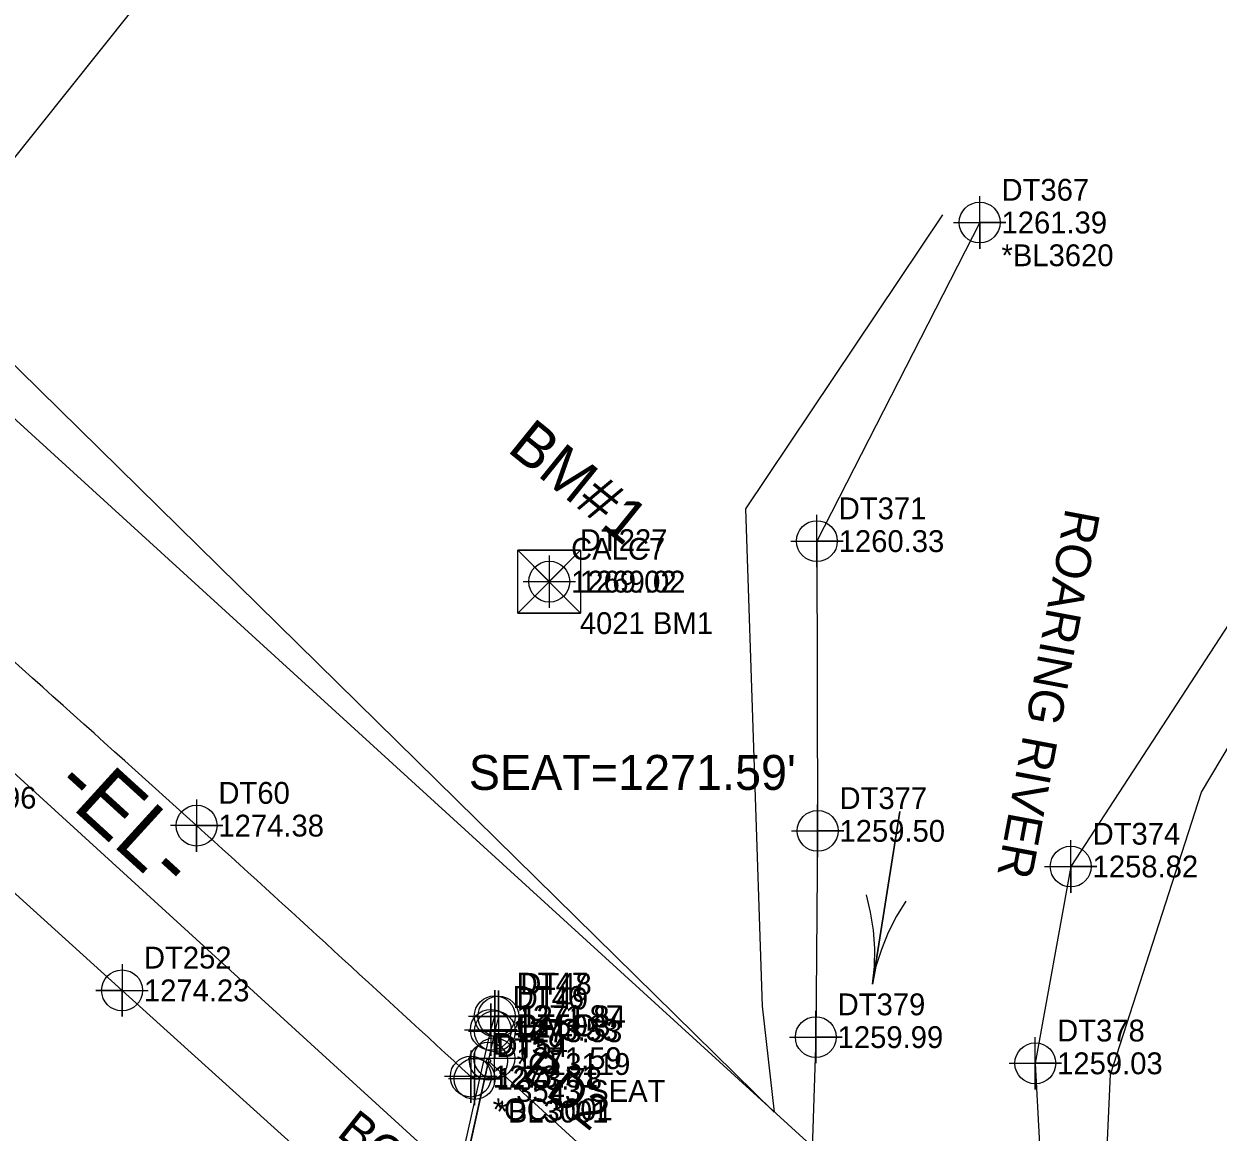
# Model space of a CAD drawing. Extents: x 1390773 to 1392296, y 959928 to 960736.
# Drawn here: x 1391507.3 to 1391644.1, y 960403.3 to 960530.2 of the extents above; entities that cross this region are included whole.
import ezdxf

# ---------------------------------------------------------------- set-up
doc = ezdxf.new("R2010")
doc.units = 0
for name, color, linetype in [('Cogo Default Point CELL', 7, 'Continuous'), ('COGO Default Point Elevation', 7, 'Continuous'), ('COGO Default Point Number', 7, 'Continuous'), ('CTL Bench Mark CELL', 7, 'Continuous'), ('CTL Bench Mark Cogo Comment', 7, 'Continuous'), ('CTL Bench Mark Cogo Elevation', 7, 'Continuous'), ('CTL Bench Mark Cogo Number', 7, 'Continuous'), ('CTL Bench Mark Text', 7, 'Continuous'), ('Default', 7, 'Continuous'), ('Exist Horizontal Alignment', 7, 'Continuous'), ('Exist Horizontal Alignment Direction Label', 7, 'Continuous'), ('Exist Hydro Jurisdictional Stream or Body of Water', 7, 'Continuous'), ('Exist Hydro River Flow Arrow CELL', 7, 'Continuous'), ('Exist Hydro Stream or Body of Water Cogo Comment', 7, 'Continuous'), ('Exist Hydro Stream or Body of Water Cogo Elevation', 7, 'Continuous'), ('Exist Hydro Stream or Body of Water Cogo Number', 7, 'Continuous'), ('Exist Hydro Stream or Body of Water Cogo Point CELL', 7, 'Continuous'), ('Exist Hydro Stream or Body of Water Text', 7, 'Continuous'), ('Exist Other Culture Located Object CELL', 7, 'Continuous'), ('Exist Other Culture Located Object Text', 7, 'Continuous'), ('Exist Right of Way Line', 7, 'Continuous'), ('Exist Roads EOP', 7, 'Continuous'), ('Exist Roads EOP Cogo Comment', 7, 'Continuous'), ('Exist Roads EOP Cogo Elevation', 7, 'Continuous'), ('Exist Roads EOP Cogo Number', 7, 'Continuous'), ('Exist Roads EOP Cogo Point CELL', 7, 'Continuous'), ('Exist Roads EOT', 7, 'Continuous'), ('Exist Roads EOT Cogo Elevation', 7, 'Continuous'), ('Exist Roads EOT Cogo Number', 7, 'Continuous'), ('Exist Roads EOT Cogo Point CELL', 7, 'Continuous'), ('Exist Structure Major Bridge Seat Top Elevation', 7, 'Continuous'), ('Exist Structure Major Bridge WW', 7, 'Continuous'), ('Exist Structure Major Bridge WW Cogo Comment', 7, 'Continuous'), ('Exist Structure Major Bridge WW Cogo Elevation', 7, 'Continuous'), ('Exist Structure Major Bridge WW Cogo Number', 7, 'Continuous'), ('Exist Structure Major Bridge WW Cogo Point CELL', 7, 'Continuous'), ('Exist Structure Major Deck Tunnel Box Culvert', 7, 'Continuous'), ('Exist Utilities Sanitary Sewer Manhole Cogo Comment', 7, 'Continuous'), ('Exist Utilities Sanitary Sewer Manhole Cogo Elevation', 7, 'Continuous'), ('Exist Utilities Sanitary Sewer Manhole Cogo Number', 7, 'Continuous'), ('Exist Vegetation Woods Line', 7, 'Continuous')]:
    doc.layers.add(name, color=color, linetype=linetype)

msp = doc.modelspace()

# ---------------------------------------------------------------- linework, layer by layer
at = {"layer": 'Cogo Default Point CELL'}
for points in [[(1391567.49, 960469.31), (1391567.49, 960466.31)], [(1391564.49, 960466.31), (1391567.49, 960466.31)], [(1391567.49, 960466.31), (1391570.49, 960466.31)], [(1391567.49, 960466.31), (1391567.49, 960463.31)], [(1391561.2, 960414.76), (1391561.2, 960411.76)], [(1391558.2, 960411.76), (1391561.2, 960411.76)], [(1391561.2, 960411.76), (1391564.2, 960411.76)], [(1391561.2, 960411.76), (1391561.2, 960408.76)]]:
    msp.add_lwpolyline(points, dxfattribs=at)
for centre in [(1391567.49, 960466.31), (1391561.2, 960411.76)]:
    msp.add_circle(centre, 2.34, dxfattribs=at)
at = {"layer": 'CTL Bench Mark CELL'}
msp.add_line((1391567.49, 960466.31), (1391567.49, 960466.31), dxfattribs=at)
msp.add_lwpolyline([(1391563.89, 960469.9), (1391571.08, 960469.9), (1391571.08, 960462.71), (1391563.89, 960462.71)], close=True, dxfattribs=at)
for points in [[(1391571.08, 960469.9), (1391563.89, 960462.71), (1391567.49, 960466.3), (1391571.08, 960462.71), (1391563.89, 960469.9)], [(1391567.49, 960466.3), (1391571.08, 960469.9), (1391563.89, 960469.9), (1391567.49, 960466.3)], [(1391567.49, 960466.3), (1391563.89, 960462.71), (1391571.08, 960462.71), (1391567.49, 960466.3)]]:
    msp.add_lwpolyline(points, dxfattribs=at)
at = {"layer": 'Default'}
msp.add_lwpolyline([(1391484.04, 960487.03), (1391533.92, 960549.51), (1391454.08, 960613.24)], dxfattribs=at)
at = {"layer": 'Exist Horizontal Alignment'}
msp.add_line((1391337.61, 960598.13), (1391677.68, 960288.07), dxfattribs=at)
at = {"layer": 'Exist Hydro Jurisdictional Stream or Body of Water'}
for points in [[(1391616.77, 960507.42), (1391598.13, 960470.95), (1391598.22, 960437.78), (1391598.01, 960414.17), (1391597.19, 960388.55), (1391595.21, 960379.53)], [(1391649.06, 960494.04), (1391648.63, 960466.55), (1391627.2, 960433.7), (1391623.14, 960411.17), (1391625.85, 960360.36), (1391624.5, 960352.95)]]:
    msp.add_lwpolyline(points, dxfattribs=at)
at = {"layer": 'Exist Hydro River Flow Arrow CELL'}
msp.add_line((1391606.06, 960430.1), (1391606.06, 960430.1), dxfattribs=at)
msp.add_lwpolyline([(1391608.32, 960429.74), (1391607.25, 960428), (1391606.31, 960426.15), (1391605.52, 960424.21), (1391604.89, 960422.24), (1391604.5, 960420.22), (1391607.62, 960439.98), (1391604.5, 960420.22), (1391604.74, 960422.26), (1391604.75, 960424.33), (1391604.6, 960426.42), (1391604.28, 960428.47), (1391603.8, 960430.46)], dxfattribs=at)
at = {"layer": 'Exist Hydro Stream or Body of Water Cogo Point CELL'}
for points in [[(1391613.77, 960507.42), (1391619.77, 960507.42), (1391616.77, 960507.42), (1391616.77, 960504.42), (1391616.77, 960510.42)], [(1391595.13, 960470.95), (1391601.13, 960470.95), (1391598.13, 960470.95), (1391598.13, 960467.95), (1391598.13, 960473.95)], [(1391595.22, 960437.78), (1391601.22, 960437.78), (1391598.22, 960437.78), (1391598.22, 960434.78), (1391598.22, 960440.78)], [(1391624.2, 960433.7), (1391630.2, 960433.7), (1391627.2, 960433.7), (1391627.2, 960430.7), (1391627.2, 960436.7)], [(1391595.01, 960414.17), (1391601.01, 960414.17), (1391598.01, 960414.17), (1391598.01, 960411.17), (1391598.01, 960417.17)], [(1391620.14, 960411.17), (1391626.14, 960411.17), (1391623.14, 960411.17), (1391623.14, 960408.17), (1391623.14, 960414.17)]]:
    msp.add_lwpolyline(points, dxfattribs=at)
for centre in [(1391616.77, 960507.42), (1391598.13, 960470.95), (1391598.22, 960437.78), (1391627.2, 960433.7), (1391598.01, 960414.17), (1391623.14, 960411.17)]:
    msp.add_circle(centre, 2.34, dxfattribs=at)
at = {"layer": 'Exist Other Culture Located Object CELL'}
for radius in [2.18, 0.24]:
    msp.add_circle((1391560.53, 960411.42), radius, dxfattribs=at)
at = {"layer": 'Exist Right of Way Line'}
msp.add_line((1391357.82, 960620.3), (1391697.89, 960310.24), dxfattribs=at)
at = {"layer": 'Exist Roads EOP'}
msp.add_line((1391558.94, 960409.38), (1391558.51, 960409.65), dxfattribs=at)
msp.add_spline([(1391558.51, 960409.65), (1391527.11, 960438.38), (1391489.56, 960472.22), (1391453.01, 960506.1), (1391416.78, 960539.25), (1391379.56, 960572.6), (1391343.96, 960605.48)], degree=3, dxfattribs=at)
at = {"layer": 'Exist Roads EOP Cogo Point CELL'}
for points in [[(1391527.11, 960441.38), (1391527.11, 960435.38), (1391527.11, 960438.38), (1391530.11, 960438.38), (1391524.11, 960438.38)], [(1391558.51, 960412.65), (1391558.51, 960406.65), (1391558.51, 960409.65), (1391561.51, 960409.65), (1391555.51, 960409.65)], [(1391558.94, 960412.38), (1391558.94, 960406.38), (1391558.94, 960409.38), (1391561.94, 960409.38), (1391555.94, 960409.38)]]:
    msp.add_lwpolyline(points, dxfattribs=at)
for centre in [(1391527.11, 960438.38), (1391558.51, 960409.65), (1391558.94, 960409.38)]:
    msp.add_circle(centre, 2.34, dxfattribs=at)
at = {"layer": 'Exist Roads EOT'}
msp.add_lwpolyline([(1391542.32, 960398.06), (1391518.58, 960419.52), (1391494.19, 960441.58), (1391465.74, 960467.93), (1391455.6, 960477.45)], dxfattribs=at)
at = {"layer": 'Exist Roads EOT Cogo Point CELL'}
msp.add_lwpolyline([(1391518.58, 960422.52), (1391518.58, 960416.52), (1391518.58, 960419.52), (1391515.58, 960419.52), (1391521.58, 960419.52)], dxfattribs=at)
msp.add_circle((1391518.58, 960419.52), 2.34, dxfattribs=at)
at = {"layer": 'Exist Structure Major Bridge WW'}
msp.add_lwpolyline([(1391553.61, 960380.47), (1391553.22, 960378.6), (1391552.75, 960378.73), (1391553.07, 960380.55), (1391560.8, 960415.01), (1391561.25, 960416.56), (1391561.67, 960416.52), (1391561.26, 960414.84), (1391553.61, 960380.47)], dxfattribs=at)
at = {"layer": 'Exist Structure Major Bridge WW Cogo Point CELL'}
for points in [[(1391558.25, 960416.56), (1391564.25, 960416.56), (1391561.25, 960416.56), (1391561.25, 960419.56), (1391561.25, 960413.56)], [(1391558.67, 960416.52), (1391564.67, 960416.52), (1391561.67, 960416.52), (1391561.67, 960419.52), (1391561.67, 960413.52)], [(1391557.8, 960415.01), (1391563.8, 960415.01), (1391560.8, 960415.01), (1391560.8, 960418.01), (1391560.8, 960412.01)], [(1391558.26, 960414.84), (1391564.26, 960414.84), (1391561.26, 960414.84), (1391561.26, 960417.84), (1391561.26, 960411.84)]]:
    msp.add_lwpolyline(points, dxfattribs=at)
for centre in [(1391561.25, 960416.56), (1391561.67, 960416.52), (1391560.8, 960415.01), (1391561.26, 960414.84)]:
    msp.add_circle(centre, 2.34, dxfattribs=at)
at = {"layer": 'Exist Structure Major Deck Tunnel Box Culvert'}
msp.add_lwpolyline([(1391654.21, 960293.41), (1391660.2, 960320.41), (1391560.53, 960411.42), (1391554.59, 960384.42), (1391654.21, 960293.41)], dxfattribs=at)
at = {"layer": 'Exist Vegetation Woods Line'}
for points in [[(1391612.53, 960508.31), (1391589.96, 960474.64), (1391591.88, 960417.73), (1391593.24, 960405.57), (1391456.79, 960539.71), (1391353.41, 960632.08)], [(1391924, 960170.47), (1391835.6, 960211.5), (1391761.23, 960261.63), (1391710.07, 960309.24), (1391644.93, 960365.54), (1391630.28, 960377.24), (1391631.75, 960409.9), (1391642.16, 960442.2), (1391654.83, 960463.47), (1391658.63, 960493.66)]]:
    msp.add_lwpolyline(points, dxfattribs=at)

# ---------------------------------------------------------------- texts
at = {"layer": 'COGO Default Point Elevation'}
for s, p in [('1269.02', (1391569.99, 960465.06)), ('1271.59', (1391563.7, 960410.51))]:
    msp.add_text(s, height=2.5, dxfattribs=at).set_placement(p)
at = {"layer": 'COGO Default Point Number'}
for s, p in [('CALC7', (1391569.99, 960468.81)), ('CALC3', (1391563.7, 960414.26))]:
    msp.add_text(s, height=2.5, dxfattribs=at).set_placement(p)
at = {"layer": 'CTL Bench Mark Cogo Comment'}
msp.add_text('4021 BM1', height=2.5, dxfattribs=at).set_placement((1391570.99, 960460.31))
at = {"layer": 'CTL Bench Mark Cogo Elevation'}
msp.add_text('1269.02', height=2.5, dxfattribs=at).set_placement((1391570.99, 960465.06))
at = {"layer": 'CTL Bench Mark Cogo Number'}
msp.add_text('DT227', height=2.5, dxfattribs=at).set_placement((1391570.99, 960469.81))
at = {"layer": 'CTL Bench Mark Text'}
msp.add_text('BM#1', height=5, rotation=321.0572, dxfattribs=at).set_placement((1391562.54, 960481.31))
at = {"layer": 'Exist Horizontal Alignment Direction Label'}
msp.add_text('-EL-', height=7, rotation=317.643, dxfattribs=at).set_placement((1391510.44, 960442.5))
at = {"layer": 'Exist Hydro Stream or Body of Water Cogo Comment'}
msp.add_text('*BL3620', height=2.5, dxfattribs=at).set_placement((1391619.27, 960502.42))
at = {"layer": 'Exist Hydro Stream or Body of Water Cogo Elevation'}
for s, p in [('1261.39', (1391619.27, 960506.17)), ('1260.33', (1391600.63, 960469.7)), ('1259.50', (1391600.72, 960436.53)), ('1258.82', (1391629.7, 960432.45)), ('1259.99', (1391600.51, 960412.92)), ('1259.03', (1391625.64, 960409.92))]:
    msp.add_text(s, height=2.5, dxfattribs=at).set_placement(p)
at = {"layer": 'Exist Hydro Stream or Body of Water Cogo Number'}
for s, p in [('DT367', (1391619.27, 960509.92)), ('DT371', (1391600.63, 960473.45)), ('DT377', (1391600.72, 960440.28)), ('DT374', (1391629.7, 960436.2)), ('DT379', (1391600.51, 960416.67)), ('DT378', (1391625.64, 960413.67))]:
    msp.add_text(s, height=2.5, dxfattribs=at).set_placement(p)
at = {"layer": 'Exist Hydro Stream or Body of Water Text'}
msp.add_text('ROARING RIVER', height=4, rotation=259.3982, dxfattribs=at).set_placement((1391626.64, 960474.83))
at = {"layer": 'Exist Other Culture Located Object Text'}
for s, p in [('BD2', (1391564.17, 960409.8)), ('BCL1', (1391543.03, 960402.94))]:
    msp.add_text(s, height=4, rotation=321.5092, dxfattribs=at).set_placement(p)
at = {"layer": 'Exist Roads EOP Cogo Comment'}
for s, p in [('*OC3001', (1391561.01, 960404.65)), ('*BL3001', (1391561.44, 960404.39))]:
    msp.add_text(s, height=2.5, dxfattribs=at).set_placement(p)
at = {"layer": 'Exist Roads EOP Cogo Elevation'}
for s, p in [('1274.38', (1391529.61, 960437.13)), ('1273.81', (1391561.01, 960408.4)), ('1273.78', (1391561.44, 960408.14))]:
    msp.add_text(s, height=2.5, dxfattribs=at).set_placement(p)
at = {"layer": 'Exist Roads EOP Cogo Number'}
for s, p in [('DT60', (1391529.61, 960440.88)), ('DT59', (1391561.01, 960412.15)), ('DT54', (1391561.44, 960411.89))]:
    msp.add_text(s, height=2.5, dxfattribs=at).set_placement(p)
at = {"layer": 'Exist Roads EOT Cogo Elevation'}
for s, p in [('1274.96', (1391496.69, 960440.33)), ('1274.23', (1391521.08, 960418.27))]:
    msp.add_text(s, height=2.5, dxfattribs=at).set_placement(p)
at = {"layer": 'Exist Roads EOT Cogo Number'}
msp.add_text('DT252', height=2.5, dxfattribs=at).set_placement((1391521.08, 960422.02))
at = {"layer": 'Exist Structure Major Bridge Seat Top Elevation'}
msp.add_text("SEAT=1271.59'", height=4, dxfattribs=at).set_placement((1391558.28, 960442.47))
at = {"layer": 'Exist Structure Major Bridge WW Cogo Comment'}
msp.add_text('*CL3119', height=2.5, dxfattribs=at).set_placement((1391563.76, 960409.84))
at = {"layer": 'Exist Structure Major Bridge WW Cogo Elevation'}
for s, p in [('1271.87', (1391563.75, 960415.31)), ('1271.84', (1391564.17, 960415.27)), ('1273.53', (1391563.3, 960413.76)), ('1273.53', (1391563.76, 960413.59))]:
    msp.add_text(s, height=2.5, dxfattribs=at).set_placement(p)
at = {"layer": 'Exist Structure Major Bridge WW Cogo Number'}
for s, p in [('DT47', (1391563.75, 960419.06)), ('DT48', (1391564.17, 960419.02)), ('DT46', (1391563.3, 960417.51)), ('DT49', (1391563.76, 960417.34))]:
    msp.add_text(s, height=2.5, dxfattribs=at).set_placement(p)
at = {"layer": 'Exist Utilities Sanitary Sewer Manhole Cogo Comment'}
msp.add_text('3543 SEAT', height=2.5, dxfattribs=at).set_placement((1391563.7, 960406.76))
at = {"layer": 'Exist Utilities Sanitary Sewer Manhole Cogo Elevation'}
msp.add_text('1271.59', height=2.5, dxfattribs=at).set_placement((1391563.7, 960410.51))
at = {"layer": 'Exist Utilities Sanitary Sewer Manhole Cogo Number'}
msp.add_text('DT50', height=2.5, dxfattribs=at).set_placement((1391563.7, 960414.26))

doc.saveas('drawing.dxf')
